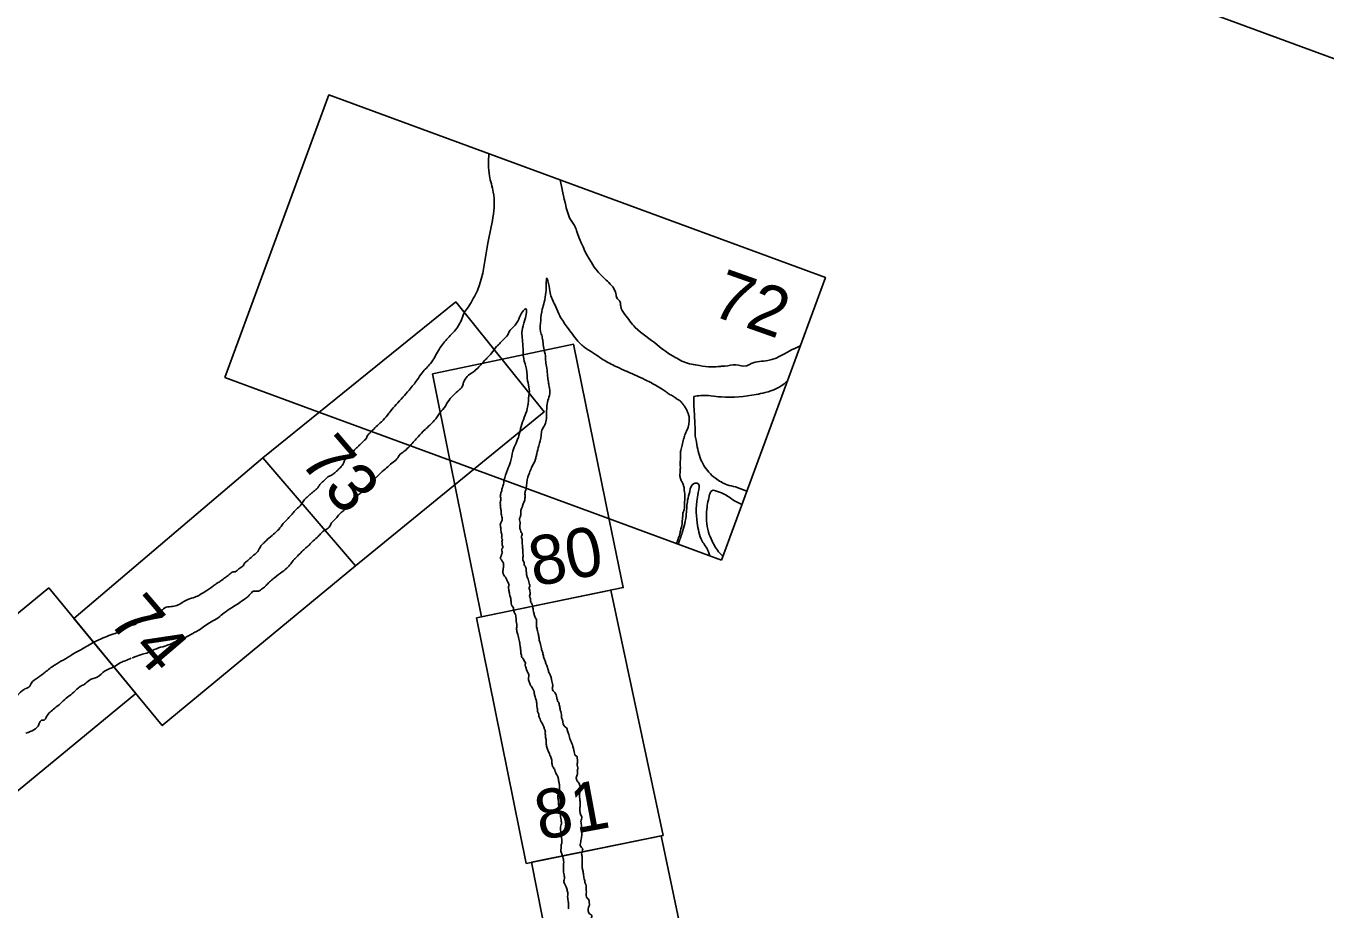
# Model space of a CAD drawing. Extents: x 3972907 to 3994831, y 172639 to 190852.
# Drawn here: x 3985354 to 3986903, y 176216 to 177268 of the extents above; entities that cross this region are included whole.
import ezdxf

# ---------------------------------------------------------------- set-up
doc = ezdxf.new("R2010")
doc.units = 0
doc.layers.add('V-ANNO-NPLT', color=7, linetype='Continuous')
doc.layers.add('V-GRID-FRAM', color=7, linetype='Continuous')

msp = doc.modelspace()

# ---------------------------------------------------------------- linework, layer by layer
at = {"layer": 'V-ANNO-NPLT'}
for p, q in [((3985636, 176753.2), (3985746.1, 176624.4)), ((3986212.4, 176713.3), (3986198.9, 176718.6)), ((3986167.9, 176637.6), (3986168.2, 176636.6))]:
    msp.add_line(p, q, dxfattribs=at)
for points in [[(3985590.6, 176848.8), (3985714.6, 177185.8), (3986306.2, 176968.3), (3986182.5, 176631.3)], [(3985636, 176753.2), (3985746.1, 176624.4), (3985971.2, 176808.1), (3985865.8, 176939.2)], [(3985865.8, 176939.2), (3985636, 176753.2)], [(3986049, 176677.8), (3986006, 176888.5), (3985919.4, 176870.4)], [(3985919.4, 176870.4), (3985837.8, 176853.3)], [(3985837.8, 176853.3), (3985858.6, 176750.5)], [(3985702.5, 176807.7), (3985590.6, 176848.8)], [(3986047.5, 176680.9), (3985702.5, 176807.7)], [(3985410.8, 176561.8), (3985636, 176753.2)], [(3985858.6, 176750.5), (3985896.5, 176563.6)], [(3985896.5, 176563.6), (3986065.3, 176598.5), (3986049, 176677.8)], [(3986182.5, 176631.3), (3986047.5, 176680.9)], [(3985410.8, 176561.8), (3985516, 176434.2), (3985746.1, 176624.4)], [(3985380.7, 176598.4), (3985166.5, 176422.1)], [(3985484.6, 176472.4), (3985380.7, 176598.4)], [(3986050.6, 176595.5), (3985890.3, 176562.4)], [(3985949.5, 176269.9), (3986112.8, 176303.3), (3986050.6, 176595.5)], [(3985949.5, 176269.9), (3985890.3, 176562.4)], [(3985166.5, 176422.1), (3985248.9, 176278.6), (3985484.6, 176472.4)], [(3986110.6, 176302.8), (3985956, 176271.3)], [(3986110.6, 176302.8), (3986172.1, 176009.6)], [(3986172.1, 176009.6), (3986013.8, 175977.8), (3985956, 176271.3)]]:
    msp.add_lwpolyline(points, dxfattribs=at)
for points in [[(3985905.2, 177115.9), (3985905.8, 177089.3), (3985910.4, 177069.9), (3985904, 177009.2), (3985891.4, 176952.8), (3985881.2, 176933.8)], [(3985905.2, 177115.8), (3985905.8, 177089.3), (3985910.4, 177069.9), (3985904, 177009.2), (3985891.4, 176952.8), (3985881.2, 176933.8)], [(3985990.1, 177084.5), (3985996.8, 177053.8), (3986003.8, 177035), (3986007.2, 177029.9), (3986009.5, 177024.2), (3986027.3, 176985.8), (3986034.5, 176975.7), (3986046.5, 176963.6), (3986056.4, 176949), (3986057.6, 176943.8), (3986061.4, 176938.9), (3986062.2, 176933.8), (3986067.3, 176924.1), (3986079.6, 176908.7), (3986105.8, 176888), (3986115.5, 176880.2), (3986129, 176871.9), (3986137.3, 176867.6), (3986156, 176863.2), (3986170.6, 176861.5), (3986181.1, 176862.2), (3986186.4, 176862.5), (3986199.5, 176864.1), (3986212, 176862.7), (3986217.7, 176865.5), (3986237.5, 176869.1), (3986275.1, 176886.1), (3986276.2, 176886.5)], [(3985949.6, 176716.6), (3985951.6, 176730.2), (3985953.5, 176735.2), (3985956.1, 176741.7), (3985959.9, 176749.4), (3985961.2, 176753.9), (3985962.2, 176757.9), (3985964.5, 176767.6), (3985967.5, 176779.7), (3985968.3, 176786), (3985971, 176790.8), (3985973.9, 176806.2), (3985974.1, 176813), (3985975.4, 176821.5), (3985977.8, 176829.7), (3985977, 176838.3), (3985976, 176843.7), (3985975.1, 176850.7), (3985974.1, 176860), (3985972.9, 176868.1), (3985972.5, 176874.7), (3985970.5, 176884), (3985969.5, 176891.9), (3985968.5, 176897.7), (3985966.7, 176903.8), (3985966.9, 176917), (3985968.7, 176930.4), (3985971.1, 176938.7), (3985973.1, 176950.3), (3985973.5, 176960.4), (3985974.1, 176967.2), (3985976.8, 176957.6), (3985978.6, 176947.9), (3985984.8, 176933.3), (3985989.7, 176922.3), (3985998.6, 176908.9), (3986011.2, 176892.3), (3986021.1, 176883.5), (3986031.1, 176877.2), (3986039.6, 176871.3), (3986054.6, 176863), (3986065.9, 176857.8), (3986078.6, 176852.1), (3986090.6, 176846.6), (3986103.7, 176839.8), (3986111.8, 176835), (3986116.2, 176832)], [(3985881.2, 176933.8), (3985875.4, 176925.2), (3985872, 176916.5), (3985865.3, 176905.8), (3985855.2, 176894.7), (3985845, 176881.2), (3985835.7, 176865.8), (3985825.6, 176854.7), (3985819.8, 176846.2), (3985810.1, 176834), (3985802.6, 176825.4), (3985794.7, 176816.8), (3985787.8, 176808.7), (3985784.4, 176804.2), (3985777.2, 176796.2), (3985770.7, 176790.4), (3985765.3, 176784.6)], [(3985811.2, 176767.7), (3985820.9, 176778.4), (3985829.1, 176786.9), (3985840, 176797.6), (3985846.8, 176806.8), (3985853.3, 176814.9), (3985856.4, 176820.1), (3985862.4, 176827.2), (3985870.2, 176834.5), (3985873.1, 176837.4), (3985874.7, 176842.3), (3985878, 176848.5), (3985884.4, 176854.3), (3985889, 176857.5), (3985894.4, 176862.9), (3985902.9, 176872.1), (3985908.2, 176877.9), (3985914.4, 176885.7), (3985923.4, 176894.9), (3985928.6, 176901.9), (3985929, 176902.9), (3985936.4, 176911.4), (3985941.8, 176921), (3985945.1, 176927.2), (3985948.9, 176930.7), (3985948, 176917.7), (3985944.7, 176904.9), (3985945.7, 176886.6), (3985946.6, 176871.6), (3985950, 176858.8), (3985951.3, 176845), (3985953.3, 176835.1), (3985952.5, 176824.5), (3985950.9, 176811.9), (3985943.5, 176790.7), (3985941, 176780), (3985937.5, 176770.7), (3985933.7, 176761.2), (3985931.1, 176748.5), (3985927.3, 176739.1), (3985923, 176726.1)], [(3986149.4, 176826.4), (3986157.5, 176827.4), (3986182, 176825.8), (3986223.5, 176828.7), (3986234.3, 176831.1), (3986259.5, 176843.7), (3986259.7, 176843.9)], [(3986116.2, 176832), (3986119.8, 176829.2), (3986125.3, 176826.3), (3986126.7, 176825.3), (3986129.6, 176823.1), (3986132.8, 176821.3), (3986135.8, 176818), (3986138.2, 176814.7), (3986140.5, 176811), (3986142.3, 176806.9), (3986143.4, 176803.4), (3986143.9, 176799.1), (3986143.2, 176793.2), (3986142.5, 176789.6), (3986140.6, 176785.1), (3986138.2, 176778.9), (3986137.1, 176775.5), (3986135.3, 176768.5), (3986134.5, 176765.2)], [(3986149.4, 176826.4), (3986149.4, 176817.4), (3986149.7, 176810.2), (3986150.2, 176802.2), (3986150.6, 176794.1), (3986150.8, 176787), (3986150.9, 176780.4), (3986152, 176774.4)], [(3985765.3, 176784.6), (3985763.4, 176782.8), (3985760.8, 176780.3), (3985759.6, 176778), (3985758.8, 176776), (3985756.2, 176773.5), (3985754.3, 176771.5), (3985751.3, 176768.8), (3985749.2, 176766.4), (3985745.7, 176763.5), (3985743.9, 176760.7), (3985739.3, 176757), (3985737.1, 176754.4), (3985733.8, 176750.9), (3985731.8, 176746.7), (3985728.3, 176741.8), (3985724.6, 176738.1), (3985720.5, 176734.6), (3985716.8, 176732.2), (3985713.4, 176730.4), (3985709.8, 176727.1), (3985706.1, 176723.8), (3985703.3, 176720.6), (3985701.3, 176717.5), (3985698.3, 176714.7), (3985695, 176712.1), (3985692, 176709.4), (3985688.5, 176706.5), (3985684.5, 176702.2), (3985681.5, 176697.5), (3985675.8, 176691.9), (3985672.4, 176688.1), (3985669, 176684.3)], [(3985811.2, 176767.7), (3985804.4, 176761), (3985799.5, 176757.4), (3985795.5, 176752), (3985789.6, 176746.9), (3985783.1, 176741.2), (3985776.6, 176735.5), (3985773.3, 176732.1), (3985766.7, 176726.1), (3985761.3, 176721.2), (3985756.8, 176716.6), (3985753.6, 176712.4), (3985749.6, 176709.3), (3985745.8, 176706.5), (3985742.9, 176704.1), (3985741.6, 176699.5), (3985738.1, 176696.6), (3985735.3, 176693.4), (3985732.3, 176690.6), (3985728.2, 176687.2), (3985723.9, 176682.2), (3985717.8, 176675.6), (3985714.7, 176670.5), (3985709.8, 176666.9)], [(3986134.5, 176765.2), (3986133.8, 176761.9), (3986133.4, 176757.3), (3986133.4, 176753.7), (3986133.4, 176751), (3986133.1, 176747.7), (3986133.3, 176742.2), (3986133.1, 176737.7), (3986132.8, 176732.6), (3986133.3, 176728.4), (3986135.3, 176724.4), (3986136.9, 176720.6), (3986137.8, 176717), (3986138, 176713.9), (3986138.4, 176712.5)], [(3986198.9, 176718.6), (3986189.1, 176721.2), (3986175, 176728.8), (3986167.2, 176736), (3986156.9, 176753.3), (3986152, 176774.4)], [(3985923, 176726.1), (3985922.3, 176720.7), (3985921.2, 176718), (3985920.7, 176716), (3985920.4, 176714), (3985919.8, 176712.3), (3985919.3, 176710.4), (3985918.8, 176708.5), (3985918.9, 176706.2), (3985919.4, 176704.2), (3985918.9, 176701.6), (3985918.8, 176698.6), (3985918.8, 176696.6), (3985919.1, 176693.7), (3985919.5, 176691.2), (3985919.8, 176689.6), (3985919.9, 176686.5), (3985920.3, 176684.3), (3985920.8, 176679), (3985919.5, 176675.7), (3985918.7, 176673.6)], [(3985949.6, 176716.6), (3985948.8, 176713.9), (3985948.1, 176710), (3985948.3, 176707.7), (3985948.1, 176705.1), (3985948.1, 176703), (3985947, 176700.7), (3985946, 176698.4), (3985945.4, 176696), (3985943.9, 176692.8), (3985943.3, 176690.6), (3985943.3, 176688.5), (3985943.4, 176686), (3985942.3, 176682.6), (3985941.6, 176679.4), (3985942.3, 176676.2), (3985942, 176672.8), (3985942.2, 176669.2), (3985942.7, 176666.9), (3985943.8, 176664.3), (3985944.9, 176662.8), (3985944.3, 176660.6), (3985943.9, 176658.9), (3985944.5, 176657), (3985944.9, 176655.3), (3985944.9, 176653.1), (3985945, 176650.7), (3985945.1, 176647.6), (3985945.4, 176645.6), (3985945.5, 176642.9), (3985945.9, 176635.8), (3985946, 176630.4), (3985947.2, 176628), (3985947.3, 176626.1), (3985948.3, 176624.1)], [(3986167.9, 176637.6), (3986166.2, 176642.6), (3986159.4, 176653.8), (3986153.4, 176675.7), (3986154.7, 176711.8), (3986154.2, 176722.5), (3986149.9, 176722.7), (3986144.4, 176713.2), (3986141.9, 176702.7), (3986140.4, 176686.5), (3986135.5, 176664), (3986130.7, 176650.3)], [(3986168.1, 176709.7), (3986169.3, 176712.3), (3986170.5, 176713.8), (3986172.4, 176714.6), (3986175.2, 176713.8)], [(3986138.4, 176712.5), (3986138.6, 176708.5), (3986138.5, 176702.8), (3986138.3, 176699.3), (3986138.2, 176696.4), (3986138.2, 176693.2), (3986136.4, 176687.6), (3986136, 176682), (3986135.6, 176678.1), (3986135.4, 176674.8), (3986133.5, 176666.3), (3986132.4, 176661.2), (3986131.2, 176658.1)], [(3986168.1, 176709.7), (3986164.8, 176691.9), (3986166.8, 176664.8), (3986171.1, 176654), (3986180.3, 176639.8), (3986184.2, 176635.9)], [(3986206.8, 176697.7), (3986197.1, 176702.5), (3986184.8, 176710.4), (3986175.2, 176713.8)], [(3985669, 176684.3), (3985664.8, 176679.7), (3985660.2, 176674.9), (3985654.8, 176668), (3985648.7, 176662.2), (3985641.1, 176655.8), (3985637.4, 176652.1), (3985633.5, 176648.2), (3985629.7, 176641.4), (3985623.2, 176635.8), (3985617.8, 176630.8), (3985614.3, 176627.9), (3985612, 176624.1), (3985607.3, 176620.9), (3985602.8, 176617.5), (3985600.4, 176617.3), (3985595.7, 176614.1), (3985591.2, 176610.7), (3985585.7, 176606.6), (3985581.6, 176603.9), (3985577.9, 176601.4), (3985575.9, 176599.8)], [(3985918.7, 176673.6), (3985919, 176671.1), (3985919.4, 176668.4), (3985919.7, 176665.3), (3985920.3, 176662.9)], [(3985709.8, 176666.9), (3985705.4, 176663.6), (3985701.8, 176659.5), (3985695.9, 176654.4), (3985690.9, 176649.3), (3985686, 176644.9), (3985681.1, 176640.2), (3985675.9, 176634.8), (3985673.3, 176632.3), (3985673.2, 176632.2)], [(3985920.3, 176662.9), (3985920.6, 176662), (3985920.6, 176660.8), (3985920.4, 176659.6), (3985920.5, 176657.8), (3985920.6, 176657.4), (3985921.1, 176656.2), (3985921.5, 176655.8), (3985920.8, 176654.8), (3985921, 176651.9), (3985921.1, 176649.6), (3985921.3, 176645.5), (3985920.5, 176644.8), (3985920.5, 176643.5), (3985921, 176641.5), (3985921.2, 176640.1), (3985921, 176639.5), (3985920.3, 176638.2)], [(3986131.2, 176658.1), (3986130.4, 176655.5), (3986129.7, 176653.9), (3986128.8, 176651)], [(3985920.3, 176638.2), (3985919.7, 176636.5), (3985919.3, 176635.4), (3985918.8, 176633.6), (3985919.4, 176632.3), (3985920.6, 176630.9), (3985921.3, 176629.5), (3985922, 176628.5), (3985922.6, 176625.7), (3985922.8, 176624.1), (3985922.5, 176622.7), (3985922.2, 176620.8), (3985922, 176619.4), (3985921.9, 176617.9), (3985921.8, 176616.4), (3985922.3, 176614.8)], [(3985647.4, 176608.6), (3985656.9, 176615.8), (3985664.4, 176621.9), (3985673.2, 176632.2)], [(3985948.3, 176624.1), (3985949.6, 176620.4), (3985949.5, 176618.8), (3985949.9, 176617), (3985950.1, 176614), (3985950.5, 176612.2), (3985952, 176608.6), (3985953.6, 176602.4), (3985953.9, 176600.4), (3985953.1, 176598.3), (3985953.8, 176595.9), (3985954.2, 176592.7), (3985954.2, 176590.6), (3985953.6, 176588.4), (3985954.6, 176585.6), (3985954.9, 176583.6), (3985955, 176581.7), (3985956.7, 176578.3), (3985957.4, 176575.4), (3985957.9, 176573.3), (3985958.3, 176570.2), (3985958.7, 176568.4), (3985959.8, 176564.2), (3985961.7, 176560.2), (3985961.8, 176556.2), (3985962, 176552), (3985963.1, 176547.1), (3985963.9, 176543.8), (3985964.8, 176539.1), (3985965.3, 176534.9), (3985966.3, 176532.6)], [(3985647.4, 176608.6), (3985646.1, 176607.4), (3985641.7, 176603.2), (3985637.9, 176599.2), (3985633, 176595.7), (3985629.7, 176594.2), (3985625.9, 176594.5), (3985621.1, 176591.3), (3985618.3, 176588.1), (3985614.1, 176584.9)], [(3985922.3, 176614.8), (3985923.9, 176612.1), (3985925.6, 176609.6), (3985927.4, 176605.8), (3985928.5, 176603.4), (3985929, 176602.4)], [(3985575.9, 176599.8), (3985567, 176593.8), (3985560.8, 176590.1), (3985555, 176587.2), (3985546.4, 176584.4), (3985540.4, 176581.1), (3985533.2, 176577.2), (3985526.6, 176576), (3985518.9, 176574.3), (3985513.4, 176569.8), (3985503.7, 176565.6), (3985495.5, 176561.2), (3985487.8, 176558.6), (3985484.8, 176555.5), (3985478.8, 176553.6), (3985465.1, 176546.2), (3985454.6, 176542.2), (3985445.7, 176538.6), (3985438.9, 176535.6), (3985434, 176533.4)], [(3985929, 176602.4), (3985929.1, 176602.2), (3985928.9, 176600.8), (3985928.6, 176599.6), (3985928.8, 176596), (3985929.6, 176592.1), (3985930.2, 176589.1), (3985931, 176586.7), (3985931.2, 176584.6), (3985931.9, 176579.7), (3985932.7, 176576.6), (3985934.4, 176574.4), (3985934.5, 176572.1), (3985935.1, 176569.8), (3985935.5, 176568.7), (3985936.8, 176566.4), (3985937.4, 176563.3), (3985937.6, 176560.5), (3985938.4, 176552.8), (3985938.3, 176547.7), (3985939.8, 176542.5), (3985940.3, 176539.3), (3985941.3, 176535.9), (3985942.4, 176529), (3985942.9, 176525), (3985943.2, 176521.9), (3985944.2, 176516.6), (3985944.7, 176515.2), (3985946.2, 176513.8), (3985947.2, 176511.2)], [(3985614.1, 176584.9), (3985599.1, 176574.7), (3985589.7, 176568.5), (3985582.7, 176562.7), (3985574.1, 176557.6), (3985566.7, 176552.9), (3985560.2, 176548.4), (3985554.7, 176545.3), (3985545.7, 176540.3), (3985533.8, 176535), (3985519.2, 176528.9), (3985509, 176525.8), (3985499.2, 176521.1), (3985492.3, 176519.1), (3985483.5, 176515.9), (3985480.3, 176514.8)], [(3985434, 176533.4), (3985420.3, 176525.3), (3985408.3, 176518.6), (3985397.9, 176512.2), (3985387.7, 176506.3), (3985376.4, 176497.7), (3985368.1, 176491.6), (3985359.8, 176484.3), (3985358.1, 176481.1), (3985352.3, 176477.8), (3985349, 176475.7), (3985342.4, 176468.8), (3985335.4, 176459.6), (3985321.4, 176445.2)], [(3985966.3, 176532.6), (3985967.7, 176525.9), (3985968.9, 176521.9), (3985969.6, 176519.5), (3985970.7, 176514.8), (3985972.2, 176511.2), (3985973.4, 176507.3), (3985974.3, 176505.6), (3985975.7, 176500.7), (3985977.2, 176496.4), (3985978.9, 176492.5), (3985979.9, 176488.9), (3985980.5, 176485.4), (3985981.4, 176482.1), (3985981, 176480.4), (3985981.1, 176476.6), (3985982.9, 176474.3), (3985985.2, 176470.7), (3985986.1, 176467.4), (3985987.1, 176463.7), (3985988.7, 176460.2), (3985989.7, 176455.2), (3985990.7, 176450.8), (3985991.5, 176447.3), (3985992.1, 176442.7), (3985993.2, 176439.3), (3985993.6, 176436.2), (3985994.9, 176433.8)], [(3985479, 176514.4), (3985471.9, 176511.3), (3985466.6, 176509.3), (3985460, 176505), (3985447.3, 176499), (3985438.6, 176492), (3985429.2, 176488.2), (3985423.4, 176483.5), (3985419.1, 176481.2), (3985416.3, 176479.3), (3985408.7, 176472.3), (3985401.5, 176466.7), (3985394.6, 176460.4), (3985388.1, 176455), (3985382.3, 176450.3), (3985378.2, 176445), (3985375.1, 176440.7), (3985372, 176440.4), (3985370.5, 176439), (3985369.1, 176435.6), (3985353.6, 176425)], [(3985947.2, 176511.2), (3985948.6, 176509.1), (3985948.5, 176507.5), (3985948.8, 176504.7), (3985949.4, 176502.5)], [(3985949.4, 176502.5), (3985950.1, 176501), (3985950.9, 176498.9), (3985951.8, 176496.7), (3985952.8, 176494.6)], [(3985952.8, 176494.6), (3985952.9, 176494), (3985952.7, 176492.2), (3985952.4, 176491.2), (3985952.3, 176488.8), (3985953.2, 176486.3), (3985954, 176484.4), (3985954.8, 176482.2), (3985955.8, 176480.7), (3985957, 176478.9), (3985957.9, 176477), (3985958.9, 176475.5), (3985959.1, 176473.8), (3985959.5, 176471.5), (3985959.9, 176469.7), (3985960.7, 176467), (3985961.6, 176464.5), (3985961.9, 176462.5), (3985962.1, 176460.8), (3985962.3, 176456.7), (3985962.9, 176454), (3985963.1, 176451)], [(3985963.1, 176451), (3985964.5, 176447.8), (3985964.8, 176445.2), (3985966.2, 176441.7), (3985967.5, 176438.8), (3985968.2, 176437.4)], [(3985968.2, 176437.4), (3985969.5, 176435.1), (3985970.9, 176431.6), (3985972.1, 176428.3), (3985972.5, 176426.3), (3985972.2, 176425)], [(3985972.2, 176425.1), (3985972.4, 176424.4), (3985972.8, 176419.9), (3985973.3, 176417.6), (3985973.5, 176411.8), (3985974.4, 176407.2), (3985976.2, 176402.9), (3985978.5, 176397.7), (3985980.1, 176392.8), (3985980.3, 176389.2), (3985981.4, 176385), (3985983.7, 176381.1), (3985984.9, 176377.9), (3985987.4, 176373.2), (3985988.1, 176369.4), (3985988.5, 176367.6), (3985988.8, 176365.8)], [(3985994.9, 176433.8), (3985996.2, 176432.4), (3985997.1, 176432), (3985998.7, 176427.9), (3986000.3, 176423.5), (3986002.3, 176416.8), (3986004.7, 176411.2), (3986006.8, 176402.8), (3986007.6, 176399.8), (3986008.1, 176398.3), (3986009, 176397.9), (3986009.6, 176398), (3986010.5, 176395.4), (3986010.9, 176391.8), (3986010.5, 176387.3), (3986011.1, 176383.8), (3986010.5, 176379.5), (3986010.5, 176375.4), (3986009.4, 176373.2), (3986009.7, 176369.8), (3986011.1, 176367.1), (3986012.7, 176365.1), (3986013.6, 176362.6), (3986013.8, 176358.2), (3986013.5, 176354), (3986013.1, 176350.1), (3986013.4, 176347.3), (3986013.4, 176345.9)], [(3985988.8, 176365.8), (3985989.4, 176361.8), (3985989.4, 176357.5), (3985989.1, 176354.7), (3985987.5, 176350.4), (3985987.8, 176345.7), (3985988, 176342.1), (3985988.2, 176339.9), (3985988.6, 176335.9), (3985990.1, 176330.2), (3985990.5, 176327.1), (3985990.8, 176323.7), (3985991.4, 176320.2), (3985991.4, 176316.2), (3985990.5, 176313), (3985990.5, 176309.5), (3985990.9, 176306.4), (3985991.2, 176303), (3985991.8, 176300.3), (3985992, 176297.5), (3985992, 176294), (3985991.3, 176292.1), (3985991.3, 176291.6)], [(3986013.4, 176345.9), (3986014.1, 176341.7), (3986013.8, 176337.5), (3986013.6, 176333), (3986014.4, 176328.6), (3986015.9, 176324.2), (3986015, 176321.3), (3986015.5, 176315.5), (3986015.8, 176311.6), (3986016.1, 176306.6), (3986015.8, 176303.2), (3986014.9, 176297.3), (3986014.4, 176294), (3986014.1, 176291.1), (3986015.5, 176289), (3986016.9, 176287.1), (3986016.7, 176285.3), (3986016.7, 176284.5)], [(3985991.3, 176291.6), (3985991.3, 176288.1), (3985991, 176284.4), (3985992.3, 176280.1), (3985993.9, 176274.4), (3985994.3, 176271.3), (3985994.1, 176267.3), (3985994.1, 176263.2), (3985994, 176259.5), (3985994.9, 176256.1), (3985995.1, 176253.9), (3985995, 176250.2), (3985994.4, 176247.9), (3985995.5, 176245.3), (3985997.4, 176241.9), (3985998.6, 176237.1), (3985999.3, 176233.6), (3985999, 176230.5), (3985999.4, 176226.8), (3985999.6, 176224)], [(3986016.7, 176284.5), (3986015.7, 176281.3), (3986016.1, 176279.5), (3986016.4, 176274), (3986016.2, 176269.2), (3986016.3, 176264.6), (3986017.3, 176260.4), (3986017.7, 176257.3), (3986018.7, 176251.5), (3986020, 176246.4), (3986020.9, 176243.1), (3986021.1, 176239.5), (3986021.3, 176235.9), (3986021.3, 176230.2), (3986022.8, 176228), (3986023.8, 176227.1), (3986024.7, 176222.9), (3986024.9, 176220.1), (3986023.8, 176217.3), (3986023.4, 176214.2), (3986024.8, 176210.2), (3986026.9, 176208.5), (3986027.9, 176207.6), (3986027, 176204.7), (3986026.5, 176202.7), (3986026.4, 176200.9), (3986026.4, 176199.6)], [(3985999.6, 176224), (3986000, 176222.6), (3986000.1, 176220.7), (3986000.2, 176218.1), (3986000.1, 176217.2), (3985999.7, 176215.6)]]:
    msp.add_spline(points, degree=3, dxfattribs=at)
at = {"layer": 'V-GRID-FRAM'}
msp.add_lwpolyline([(3976065.4, 181215.5), (3978987, 189164.4), (3993292.9, 183906.2), (3990371.3, 175957.4), (3976065.4, 181215.5)], dxfattribs=at)

# ---------------------------------------------------------------- texts
at = {"layer": 'V-ANNO-NPLT'}
for s, rotation, p in [('72', 340.531, (3986167.8, 176924)), ('73', 310.531, (3985678.1, 176748.8)), ('80', 10.531, (3985958.9, 176599.7)), ('74', 310.531, (3985450.2, 176558.5)), ('81', 10.531, (3985966, 176297.4))]:
    msp.add_text(s, height=58.5, rotation=rotation, dxfattribs=at).set_placement(p)

doc.saveas('drawing.dxf')
